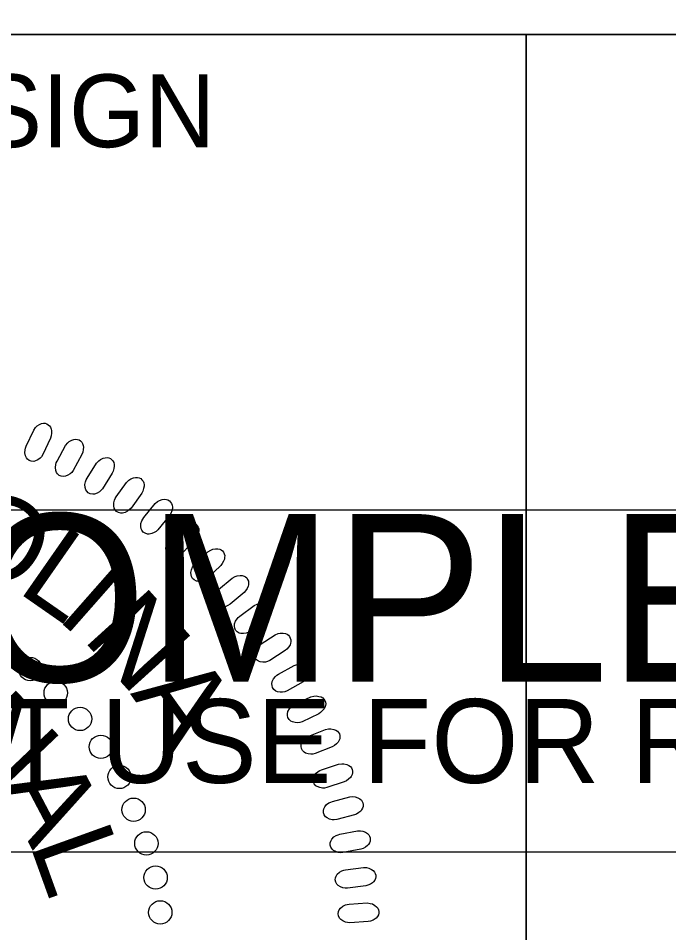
# Model space of a CAD drawing. Extents: x 505692 to 507376, y 438761 to 439861.
# Drawn here: x 507223.8 to 507268.5, y 439749.4 to 439812.2 of the extents above; entities that cross this region are included whole.
import ezdxf

# ---------------------------------------------------------------- set-up
doc = ezdxf.new("R2010")
doc.units = 0
for name, color, linetype in [('Sheet PE Seal Cell', 7, 'Continuous'), ('Sheet Profile CELL', 7, 'Continuous'), ('Sheet Sticker Incomplete CELL', 7, 'Continuous')]:
    doc.layers.add(name, color=color, linetype=linetype)

msp = doc.modelspace()

# ---------------------------------------------------------------- linework, layer by layer
at = {"layer": 'Sheet PE Seal Cell'}
for points in [[(507224.353, 439782.815), (507224.876, 439783.924), (507225.003, 439784.107), (507225.11, 439784.211), (507225.284, 439784.317), (507225.418, 439784.375), (507225.554, 439784.399), (507225.665, 439784.39), (507225.775, 439784.36), (507225.868, 439784.294), (507225.964, 439784.217), (507226.033, 439784.118), (507226.085, 439783.983), (507226.105, 439783.886), (507226.102, 439783.721), (507226.08, 439783.534), (507226.033, 439783.379), (507225.504, 439782.239), (507225.411, 439782.096), (507225.311, 439781.988), (507225.162, 439781.882), (507225.001, 439781.804), (507224.879, 439781.773), (507224.711, 439781.785), (507224.568, 439781.832), (507224.45, 439781.931), (507224.376, 439782.021), (507224.304, 439782.165), (507224.268, 439782.369), (507224.283, 439782.561), (507224.312, 439782.69)], [(507226.477, 439781.799), (507227.068, 439782.874), (507227.207, 439783.048), (507227.32, 439783.145), (507227.5, 439783.24), (507227.638, 439783.289), (507227.775, 439783.305), (507227.886, 439783.289), (507227.994, 439783.253), (507228.082, 439783.181), (507228.172, 439783.097), (507228.235, 439782.995), (507228.279, 439782.857), (507228.293, 439782.758), (507228.28, 439782.595), (507228.245, 439782.408), (507228.189, 439782.258), (507227.589, 439781.153), (507227.488, 439781.016), (507227.381, 439780.915), (507227.226, 439780.818), (507227.06, 439780.75), (507226.937, 439780.727), (507226.77, 439780.75), (507226.63, 439780.805), (507226.518, 439780.911), (507226.45, 439781.006), (507226.387, 439781.155), (507226.364, 439781.361), (507226.391, 439781.55), (507226.428, 439781.679)], [(507228.535, 439780.614), (507229.193, 439781.65), (507229.342, 439781.815), (507229.461, 439781.904), (507229.646, 439781.988), (507229.788, 439782.029), (507229.925, 439782.036), (507230.034, 439782.013), (507230.14, 439781.97), (507230.224, 439781.893), (507230.308, 439781.803), (507230.365, 439781.697), (507230.4, 439781.557), (507230.407, 439781.457), (507230.384, 439781.294), (507230.339, 439781.111), (507230.272, 439780.964), (507229.605, 439779.9), (507229.494, 439779.769), (507229.382, 439779.675), (507229.221, 439779.588), (507229.052, 439779.53), (507228.926, 439779.515), (507228.761, 439779.549), (507228.625, 439779.612), (507228.52, 439779.726), (507228.459, 439779.824), (507228.404, 439779.977), (507228.395, 439780.183), (507228.434, 439780.371), (507228.479, 439780.497)], [(507230.535, 439779.341), (507231.256, 439780.333), (507231.416, 439780.489), (507231.54, 439780.571), (507231.73, 439780.642), (507231.873, 439780.674), (507232.011, 439780.673), (507232.12, 439780.643), (507232.222, 439780.593), (507232.301, 439780.512), (507232.38, 439780.417), (507232.429, 439780.307), (507232.455, 439780.165), (507232.457, 439780.065), (507232.423, 439779.904), (507232.366, 439779.724), (507232.29, 439779.582), (507231.557, 439778.561), (507231.439, 439778.437), (507231.321, 439778.351), (507231.155, 439778.274), (507230.982, 439778.227), (507230.856, 439778.22), (507230.694, 439778.264), (507230.562, 439778.336), (507230.464, 439778.456), (507230.409, 439778.558), (507230.365, 439778.713), (507230.368, 439778.92), (507230.419, 439779.105), (507230.471, 439779.228)], [(507232.43, 439777.925), (507233.212, 439778.87), (507233.38, 439779.015), (507233.51, 439779.089), (507233.704, 439779.149), (507233.849, 439779.171), (507233.986, 439779.161), (507234.092, 439779.125), (507234.192, 439779.068), (507234.265, 439778.982), (507234.338, 439778.882), (507234.381, 439778.77), (507234.398, 439778.626), (507234.393, 439778.527), (507234.349, 439778.369), (507234.281, 439778.192), (507234.197, 439778.055), (507233.401, 439777.082), (507233.275, 439776.965), (507233.152, 439776.887), (507232.981, 439776.821), (507232.805, 439776.785), (507232.68, 439776.785), (507232.521, 439776.839), (507232.393, 439776.92), (507232.303, 439777.046), (507232.254, 439777.151), (507232.22, 439777.308), (507232.236, 439777.515), (507232.299, 439777.697), (507232.359, 439777.815)], [(507234.201, 439776.411), (507235.041, 439777.305), (507235.219, 439777.439), (507235.352, 439777.505), (507235.55, 439777.552), (507235.696, 439777.565), (507235.832, 439777.547), (507235.936, 439777.504), (507236.032, 439777.442), (507236.1, 439777.351), (507236.166, 439777.247), (507236.202, 439777.132), (507236.21, 439776.987), (507236.199, 439776.888), (507236.145, 439776.733), (507236.066, 439776.561), (507235.973, 439776.43), (507235.118, 439775.509), (507234.985, 439775.401), (507234.857, 439775.33), (507234.682, 439775.275), (507234.506, 439775.25), (507234.379, 439775.258), (507234.224, 439775.322), (507234.101, 439775.41), (507234.02, 439775.541), (507233.978, 439775.649), (507233.954, 439775.809), (507233.983, 439776.014), (507234.056, 439776.191), (507234.124, 439776.306)], [(507235.946, 439774.717), (507236.84, 439775.557), (507237.026, 439775.679), (507237.163, 439775.737), (507237.363, 439775.771), (507237.51, 439775.776), (507237.645, 439775.749), (507237.746, 439775.7), (507237.837, 439775.632), (507237.899, 439775.536), (507237.959, 439775.428), (507237.987, 439775.311), (507237.986, 439775.166), (507237.969, 439775.068), (507237.906, 439774.917), (507237.816, 439774.751), (507237.715, 439774.625), (507236.803, 439773.76), (507236.665, 439773.66), (507236.532, 439773.597), (507236.355, 439773.553), (507236.176, 439773.539), (507236.051, 439773.556), (507235.9, 439773.629), (507235.783, 439773.725), (507235.71, 439773.861), (507235.675, 439773.971), (507235.66, 439774.132), (507235.702, 439774.335), (507235.787, 439774.508), (507235.862, 439774.618)], [(507237.557, 439772.971), (507238.503, 439773.753), (507238.696, 439773.864), (507238.837, 439773.913), (507239.039, 439773.934), (507239.186, 439773.929), (507239.319, 439773.893), (507239.416, 439773.838), (507239.503, 439773.765), (507239.559, 439773.665), (507239.612, 439773.554), (507239.633, 439773.435), (507239.622, 439773.291), (507239.599, 439773.194), (507239.526, 439773.047), (507239.426, 439772.887), (507239.318, 439772.768), (507238.354, 439771.961), (507238.209, 439771.87), (507238.073, 439771.816), (507237.893, 439771.784), (507237.713, 439771.781), (507237.59, 439771.805), (507237.443, 439771.887), (507237.333, 439771.991), (507237.269, 439772.131), (507237.24, 439772.243), (507237.236, 439772.405), (507237.291, 439772.605), (507237.386, 439772.771), (507237.467, 439772.877)], [(507239.018, 439771.149), (507240.011, 439771.869), (507240.21, 439771.968), (507240.354, 439772.008), (507240.557, 439772.017), (507240.703, 439772.002), (507240.833, 439771.959), (507240.927, 439771.897), (507241.009, 439771.818), (507241.059, 439771.715), (507241.105, 439771.602), (507241.118, 439771.482), (507241.098, 439771.338), (507241.069, 439771.243), (507240.987, 439771.1), (507240.877, 439770.947), (507240.762, 439770.835), (507239.749, 439770.091), (507239.599, 439770.01), (507239.459, 439769.963), (507239.278, 439769.942), (507239.098, 439769.951), (507238.977, 439769.983), (507238.836, 439770.075), (507238.732, 439770.184), (507238.677, 439770.328), (507238.656, 439770.442), (507238.661, 439770.604), (507238.729, 439770.8), (507238.834, 439770.96), (507238.922, 439771.061)], [(507240.418, 439769.202), (507241.454, 439769.86), (507241.66, 439769.946), (507241.806, 439769.977), (507242.009, 439769.973), (507242.154, 439769.949), (507242.281, 439769.897), (507242.371, 439769.83), (507242.448, 439769.746), (507242.491, 439769.641), (507242.53, 439769.524), (507242.535, 439769.404), (507242.507, 439769.261), (507242.472, 439769.168), (507242.381, 439769.031), (507242.262, 439768.885), (507242.139, 439768.78), (507241.082, 439768.101), (507240.927, 439768.029), (507240.785, 439767.993), (507240.602, 439767.983), (507240.424, 439768.002), (507240.304, 439768.042), (507240.17, 439768.142), (507240.073, 439768.258), (507240.027, 439768.405), (507240.013, 439768.52), (507240.029, 439768.682), (507240.108, 439768.873), (507240.224, 439769.026), (507240.317, 439769.121)], [(507241.679, 439767.153), (507242.755, 439767.743), (507242.965, 439767.816), (507243.112, 439767.838), (507243.315, 439767.822), (507243.458, 439767.789), (507243.582, 439767.729), (507243.667, 439767.656), (507243.739, 439767.568), (507243.775, 439767.46), (507243.806, 439767.341), (507243.805, 439767.22), (507243.768, 439767.08), (507243.726, 439766.99), (507243.628, 439766.858), (507243.499, 439766.72), (507243.37, 439766.623), (507242.272, 439766.012), (507242.113, 439765.95), (507241.968, 439765.922), (507241.786, 439765.924), (507241.61, 439765.955), (507241.492, 439766.001), (507241.365, 439766.11), (507241.275, 439766.232), (507241.238, 439766.381), (507241.231, 439766.497), (507241.258, 439766.657), (507241.349, 439766.843), (507241.474, 439766.989), (507241.573, 439767.078)], [(507242.787, 439765.07), (507243.897, 439765.592), (507244.111, 439765.651), (507244.26, 439765.664), (507244.461, 439765.634), (507244.602, 439765.592), (507244.722, 439765.525), (507244.802, 439765.447), (507244.868, 439765.354), (507244.898, 439765.244), (507244.921, 439765.123), (507244.912, 439765.003), (507244.866, 439764.866), (507244.819, 439764.778), (507244.712, 439764.653), (507244.575, 439764.523), (507244.44, 439764.435), (507243.306, 439763.893), (507243.144, 439763.842), (507242.998, 439763.823), (507242.816, 439763.836), (507242.642, 439763.878), (507242.528, 439763.932), (507242.407, 439764.049), (507242.325, 439764.176), (507242.298, 439764.328), (507242.299, 439764.444), (507242.334, 439764.602), (507242.438, 439764.782), (507242.571, 439764.919), (507242.676, 439765.001)], [(507243.766, 439762.908), (507244.907, 439763.36), (507245.125, 439763.405), (507245.274, 439763.409), (507245.472, 439763.367), (507245.61, 439763.316), (507245.726, 439763.242), (507245.801, 439763.159), (507245.861, 439763.062), (507245.883, 439762.95), (507245.9, 439762.828), (507245.883, 439762.709), (507245.828, 439762.575), (507245.777, 439762.49), (507245.662, 439762.372), (507245.517, 439762.25), (507245.377, 439762.171), (507244.211, 439761.702), (507244.046, 439761.66), (507243.899, 439761.651), (507243.718, 439761.676), (507243.547, 439761.728), (507243.436, 439761.79), (507243.323, 439761.914), (507243.25, 439762.045), (507243.232, 439762.199), (507243.24, 439762.315), (507243.285, 439762.47), (507243.4, 439762.643), (507243.542, 439762.772), (507243.652, 439762.847)], [(507244.64, 439760.594), (507245.808, 439760.973), (507246.028, 439761.005), (507246.177, 439760.999), (507246.372, 439760.944), (507246.507, 439760.886), (507246.617, 439760.804), (507246.687, 439760.717), (507246.741, 439760.616), (507246.757, 439760.503), (507246.765, 439760.38), (507246.741, 439760.263), (507246.678, 439760.132), (507246.621, 439760.05), (507246.499, 439759.94), (507246.347, 439759.828), (507246.202, 439759.757), (507245.009, 439759.362), (507244.841, 439759.331), (507244.694, 439759.331), (507244.515, 439759.367), (507244.348, 439759.43), (507244.241, 439759.498), (507244.135, 439759.629), (507244.071, 439759.765), (507244.063, 439759.92), (507244.078, 439760.034), (507244.133, 439760.186), (507244.257, 439760.352), (507244.408, 439760.472), (507244.522, 439760.54)], [(507245.385, 439758.421), (507246.573, 439758.725), (507246.795, 439758.744), (507246.943, 439758.729), (507247.136, 439758.662), (507247.266, 439758.595), (507247.371, 439758.506), (507247.436, 439758.415), (507247.483, 439758.311), (507247.492, 439758.197), (507247.492, 439758.074), (507247.461, 439757.958), (507247.39, 439757.832), (507247.327, 439757.754), (507247.199, 439757.652), (507247.04, 439757.549), (507246.891, 439757.488), (507245.676, 439757.169), (507245.506, 439757.148), (507245.359, 439757.157), (507245.182, 439757.204), (507245.02, 439757.278), (507244.918, 439757.352), (507244.821, 439757.489), (507244.765, 439757.629), (507244.766, 439757.784), (507244.788, 439757.898), (507244.854, 439758.046), (507244.988, 439758.203), (507245.145, 439758.313), (507245.264, 439758.374)], [(507245.895, 439756.167), (507247.1, 439756.396), (507247.322, 439756.4), (507247.469, 439756.376), (507247.657, 439756.297), (507247.783, 439756.222), (507247.883, 439756.127), (507247.941, 439756.032), (507247.982, 439755.925), (507247.983, 439755.812), (507247.975, 439755.688), (507247.937, 439755.575), (507247.858, 439755.453), (507247.791, 439755.379), (507247.656, 439755.285), (507247.491, 439755.193), (507247.339, 439755.141), (507246.106, 439754.898), (507245.935, 439754.889), (507245.79, 439754.907), (507245.616, 439754.965), (507245.458, 439755.049), (507245.362, 439755.129), (507245.273, 439755.273), (507245.226, 439755.416), (507245.237, 439755.57), (507245.266, 439755.682), (507245.34, 439755.826), (507245.485, 439755.974), (507245.649, 439756.075), (507245.77, 439756.128)], [(507246.293, 439753.728), (507247.51, 439753.881), (507247.732, 439753.871), (507247.878, 439753.837), (507248.06, 439753.747), (507248.181, 439753.665), (507248.274, 439753.563), (507248.327, 439753.465), (507248.36, 439753.356), (507248.355, 439753.242), (507248.34, 439753.119), (507248.294, 439753.008), (507248.208, 439752.892), (507248.136, 439752.823), (507247.996, 439752.737), (507247.825, 439752.655), (507247.67, 439752.613), (507246.424, 439752.448), (507246.253, 439752.45), (507246.109, 439752.477), (507245.94, 439752.546), (507245.787, 439752.64), (507245.696, 439752.726), (507245.616, 439752.874), (507245.578, 439753.021), (507245.599, 439753.173), (507245.636, 439753.283), (507245.719, 439753.422), (507245.872, 439753.562), (507246.042, 439753.651), (507246.167, 439753.696)], [(507246.537, 439751.363), (507247.761, 439751.439), (507247.982, 439751.415), (507248.125, 439751.373), (507248.301, 439751.271), (507248.416, 439751.181), (507248.503, 439751.074), (507248.549, 439750.972), (507248.576, 439750.861), (507248.563, 439750.748), (507248.541, 439750.627), (507248.488, 439750.519), (507248.395, 439750.408), (507248.319, 439750.344), (507248.174, 439750.267), (507247.998, 439750.196), (507247.841, 439750.164), (507246.587, 439750.078), (507246.416, 439750.09), (507246.274, 439750.126), (507246.109, 439750.205), (507245.963, 439750.308), (507245.877, 439750.4), (507245.808, 439750.553), (507245.778, 439750.702), (507245.809, 439750.853), (507245.852, 439750.961), (507245.944, 439751.094), (507246.105, 439751.223), (507246.281, 439751.302), (507246.408, 439751.34)]]:
    msp.add_lwpolyline(points, close=True, dxfattribs=at)
for centre in [(507224.634, 439767.508), (507226.385, 439765.874), (507228.056, 439764.081), (507229.489, 439762.168), (507230.762, 439760.096), (507231.735, 439757.847), (507232.61, 439755.536), (507233.246, 439753.186), (507233.564, 439750.795)]:
    msp.add_circle(centre, 0.801, dxfattribs=at)
at = {"layer": 'Sheet Profile CELL'}
msp.add_line((507258.678, 439811.094), (507258.678, 439698.644), dxfattribs=at)
for points in [[(507158.628, 439836.144), (507358.678, 439836.144), (507358.678, 439811.094), (507158.628, 439811.094)], [(507158.628, 439811.094), (507258.678, 439811.094), (507258.678, 439698.594), (507158.628, 439698.594)], [(507258.678, 439811.094), (507358.678, 439811.094), (507358.678, 439698.594), (507258.678, 439698.594)]]:
    msp.add_lwpolyline(points, close=True, dxfattribs=at)
at = {"layer": 'Sheet Sticker Incomplete CELL'}
msp.add_lwpolyline([(507185.195, 439754.938), (507185.195, 439778.438), (507332.195, 439778.438), (507332.195, 439754.938)], close=True, dxfattribs=at)

# ---------------------------------------------------------------- texts
at = {"layer": 'Sheet PE Seal Cell'}
for s, rotation, p in [('O', 331.63025, (507218.924, 439775.405)), ('L', 325.14089, (507223.657, 439772.874)), ('I', 318.65154, (507226.35, 439771.021)), ('N', 312.16218, (507228.155, 439769.601)), ('A', 305.67282, (507231.475, 439765.821)), ('N', 313.65025, (507219.122, 439762.563)), ('A', 297.77065, (507222.459, 439759.482)), ('L', 289.83086, (507224.583, 439755.487))]:
    msp.add_text(s, height=5.669, rotation=rotation, dxfattribs=at).set_placement(p)
at = {"layer": 'Sheet Profile CELL'}
msp.add_text('ROADWAY DESIGN', height=5.0001, dxfattribs=at).set_placement((507175.29, 439803.357))
at = {"layer": 'Sheet Sticker Incomplete CELL'}
for s, height, p in [('INCOMPLETE PLANS', 11.52, (507194.145, 439766.638)), ('DO NOT USE FOR R/W ACQUISITION', 5.76, (507197.395, 439759.688))]:
    msp.add_text(s, height=height, dxfattribs=at).set_placement(p)

doc.saveas('drawing.dxf')
